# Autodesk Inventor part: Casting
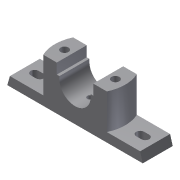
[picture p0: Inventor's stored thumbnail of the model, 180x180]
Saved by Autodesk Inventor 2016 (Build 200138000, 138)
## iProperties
Created: 2009-04
Part Number: Casting
Document SubType Name: Modeling
Designer: Sham
Density: 1 g/cm^3
Material: Generic
Appearance: Default
Author: Sham
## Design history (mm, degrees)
sketch "Sketch1"
  geometry: L1 (-104, 0)-(104, 0); L2 (-104, 0)-(-100, 14); L3 (-100, 14)-(100, 14); L4 (100, 14)-(104, 0); 1 further point
  constraints: 8 end point, 1 horizontal, 1 midpoint, 1 parallel, 1 other
  dimensions: "d0" = 208 distance of L1.start L1.end; "d1" = 104 distance of L1.end point (0, 0); "d2" = 4 horizontal distance of L1.start L2.end; "d3" = 4 horizontal distance of L1.end L3.end; "d10" = 14 distance between parallel lines of L1 L3
extrude "Extrusion1" new body sketch "Sketch1" stored distance "d4" = 46; taper "d5" = 0 deg
sketch "Sketch2"
  geometry: L1 (51.143, 46)-(148.857, 46); L2 (148.857, 0)-(51.143, 0); A1 r 54 centre (100, 23) between (51.143, 46) and (51.143, 0); A2 r 54 centre (100, 23) between (148.857, 0) and (148.857, 46)
  constraints: 4 end point, 4 point on circle, 2 centre point, 1 parallel
extrude "Extrusion2" join sketch "Sketch2" distance "d8" = 54; taper "d9" = 0 deg
sketch "Sketch3"
  geometry: L1 (-28, 68)-(-28, 52); L2 (-28, 52)-(-24, 52); L3 (28, 68)-(28, 52); L4 (28, 52)-(24, 52); L5 (-28, 68)-(28, 68); L6 (-100, 14)-(-48.857, 14) reference; L7 (0, 48)-(0, 19); L8 (48.857, 14)-(100, 14) reference; L9 (48.857, 68)-(-48.857, 68) reference; L10 (-24, 48)-(-24, 52); L11 (24, 48)-(24, 52); A1 r 24 centre (0, 48) between (-24, 48) and (24, 48); 1 further point
  constraints: 16 end point, 5 perpendicular, 2 point on circle, 2 symmetric about line, 1 centre point, 1 tangent, 1 vertical alignment, 1 other
  dimensions: "d11" = 16 distance of L1.start L1.end; "d16" = 24 radius of A1; "d17" = 16 distance of L3.start L3.end; "d52" = 56 distance between parallel lines of L1 L3; "d54" = 54 distance between parallel lines of L8 L9 (derived)
extrude "Extrusion3" cut sketch "Sketch3" distance "d18" = 54; taper "d19" = 0 deg
sketch "Sketch4"
  geometry: L1 (-23, 29)-(-15, 29); L2 (-15, 17)-(-23, 17); L3 (-185, 29)-(-177, 29); L4 (-177, 17)-(-185, 17); A1 r 6 centre (-15, 23) between (-15, 17) and (-15, 29); A2 r 6 centre (-23, 23) between (-23, 29) and (-23, 17); A3 r 6 centre (-177, 23) between (-177, 17) and (-177, 29); A4 r 6 centre (-185, 23) between (-185, 29) and (-185, 17)
  constraints: 8 end point, 8 point on circle, 8 tangent, 4 centre point, 3 parallel
  dimensions: "d20" = 8 distance of A1.centre A2.centre; "d21" = 6 radius of A1; "d24" = 6 radius of A3; "d25" = 8 distance of A4.centre A3.centre
extrude "Extrusion4" cut sketch "Sketch4" distance "d28" = 54; taper "d29" = 0 deg
sketch "Sketch5"
  geometry: L1 (208, 0)-(0, 0) reference; L2 (52, -10)-(78, -10); L3 (78, -10)-(78, -36); L4 (78, -36)-(52, -36); L5 (52, -36)-(52, -10); L6 (130, -10)-(156, -10); L7 (156, -10)-(156, -36); L8 (156, -36)-(130, -36); L9 (130, -36)-(130, -10); L10 (0, -46)-(208, -46) reference; L11 (104, -23)-(104, -46)
  constraints: 18 end point, 5 perpendicular, 4 parallel, 2 horizontal, 1 midpoint
  dimensions: "d30" = 26 distance of L2.start L2.end; "d31" = 10 distance between parallel lines of L2 L1; "d32" = 10 distance between parallel lines of L1 L6; "d65" = 26 distance between parallel lines of L3 L11; "d66" = 26 distance between parallel lines of L9 L11
extrude "Extrusion5" cut sketch "Sketch5" distance "d34" = 10; taper "d35" = 0 deg
sketch "Sketch6"
  geometry: L1 (148.857, 0)-(128, 0) reference; L2 (72, 0)-(51.143, 0) reference; L3 (0, 46)-(0, 0) reference; L4 (200, 46)-(200, 0) reference; C1 r 6 at (61, 23); C2 r 6 at (139, 23); 1 further point
  constraints: 2 centre point, 1 equal radius
  dimensions: "d36" = 12 diameter of C1; "d37" = 78 distance of C2.centre C1.centre; "d39" = 39 distance of C2.centre point (100, 23); "d58" = 39 distance of C1.centre point (100, 23); "d59" = 23 distance from line of L1 C2.centre; "d60" = 23 distance from line of L2 C1.centre; "d61" = 61 distance from line of L3 C1.centre; "d62" = 61 distance from line of L4 C2.centre (derived)
extrude "Extrusion6" cut sketch "Sketch6" stored distance "d40" = 10; taper "d41" = 0 deg
workplane "Work Plane1"
sketch "Sketch7"
  geometry: L1 (-4, 46)-(204, 46) reference; L2 (-4, 0)-(-4, 46) reference; 1 further point
  dimensions: "d43" = 23 distance from line of L1 point (100, 23); "d44" = 104 distance from line of point (100, 23) L2
hole "Hole1" sketch "Sketch7" at (100, 23) diameter "d45" = 8; stored, may be unused: countersink angle "d49" = 90 deg, drill point angle "d51" = 118 deg; dims "d46" = 6, "d47" = 8, "d48" = 16, "d50" = 8
body "Solid1"
other parameters: "d6" = 108, "d42" = -52
